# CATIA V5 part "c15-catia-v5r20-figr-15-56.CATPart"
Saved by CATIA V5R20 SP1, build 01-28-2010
Part number: Part1
Bounding box of the stored display mesh (mm): x -75 to -29.087, y -20 to 20, z 0 to 62.461
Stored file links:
  D:\v5_r20\psrt_files_downloaded\c15\c15-catia-v5r20-figr-15-56.CATPart
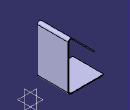
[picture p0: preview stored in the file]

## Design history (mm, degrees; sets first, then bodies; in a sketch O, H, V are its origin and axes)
SheetMetalParameters1: Thickness 1, BendRadius 2, KFactor 0.400515 {= log(min(100,max(20*SheetMetalParameters1.BendRadius,SheetMetalParameters1.Thickness)/SheetMetalParameters1.Thickness))/log(100)/2}, ReliefRadialLength 1, ReliefAxialLength 2, MinimumBendRadius 0
Body1 (main body)
  Sketch1 on xy-plane, origin (0, 0, 0), H (1, 0, 0), V (0, 1, 0)
    line L1 (-75, 20) -> (75, 20)
    line L2 (75, 20) -> (75, -20)
    line L3 (75, -20) -> (-75, -20)
    line L4 (-75, -20) -> (-75, 20)
    distance L1 L3 = 40
    distance L2 L4 = 150
    distance V L2 = 75
    distance H L3 = 20
    horizontal: L1 H, L3 H
    vertical: L2 V, L4 V
  Wall1: Thickness 1, Profile Sketch1
  Sketch2 on face of Wall1, origin (0, 0, 1), H (1, 0, 0), V (0, 1, 0)
    line L1 (-30.2021, 19.5432) -> (-30.2021, -20.6466)
    line L2 (31.0296, 19.5432) -> (31.0296, -20.6466)
    vertical: L1 V, L2 V
  FlatBend1: FlatBendAngle 90, FlatBendAngle 45, Axis Sketch2, FixedPoint vertex [face of Wall1 | face of Wall1 | face of Wall1], FlatBendKFactor 0.400515 {= log(min(100,max(20*FlatBend1.FlatBendRadius,SheetMetalParameters1.Thickness)/SheetMetalParameters1.Thickness))/log(100)/2}, FlatBendKFactor 0.400515 {= log(min(100,max(20*FlatBend1.FlatBendRadius,SheetMetalParameters1.Thickness)/SheetMetalParameters1.Thickness))/log(100)/2}, FlatBendRadius 2 {= SheetMetalParameters1.BendRadius}, FlatBendRadius 2 {= SheetMetalParameters1.BendRadius}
